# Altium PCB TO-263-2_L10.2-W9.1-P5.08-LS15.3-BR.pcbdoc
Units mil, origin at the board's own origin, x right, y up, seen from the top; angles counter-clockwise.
Board outline 1178.05 x 916 mil, 2 copper layers (Top Layer, Bottom Layer), stack 0 mil thick; 1 components, 0 nets, 3 pads, 0 vias.
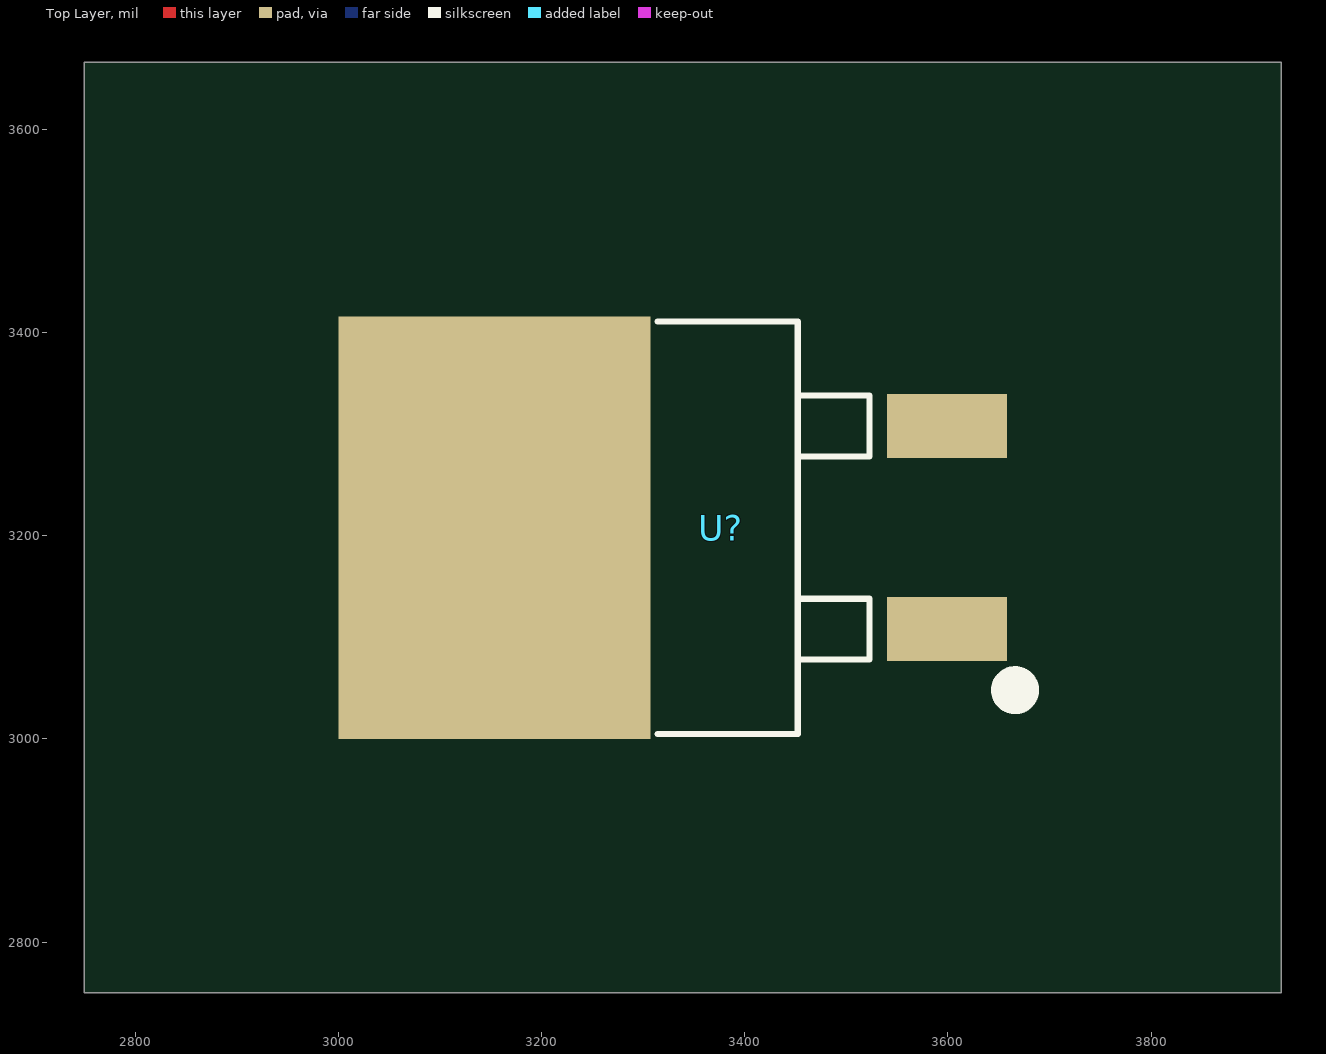
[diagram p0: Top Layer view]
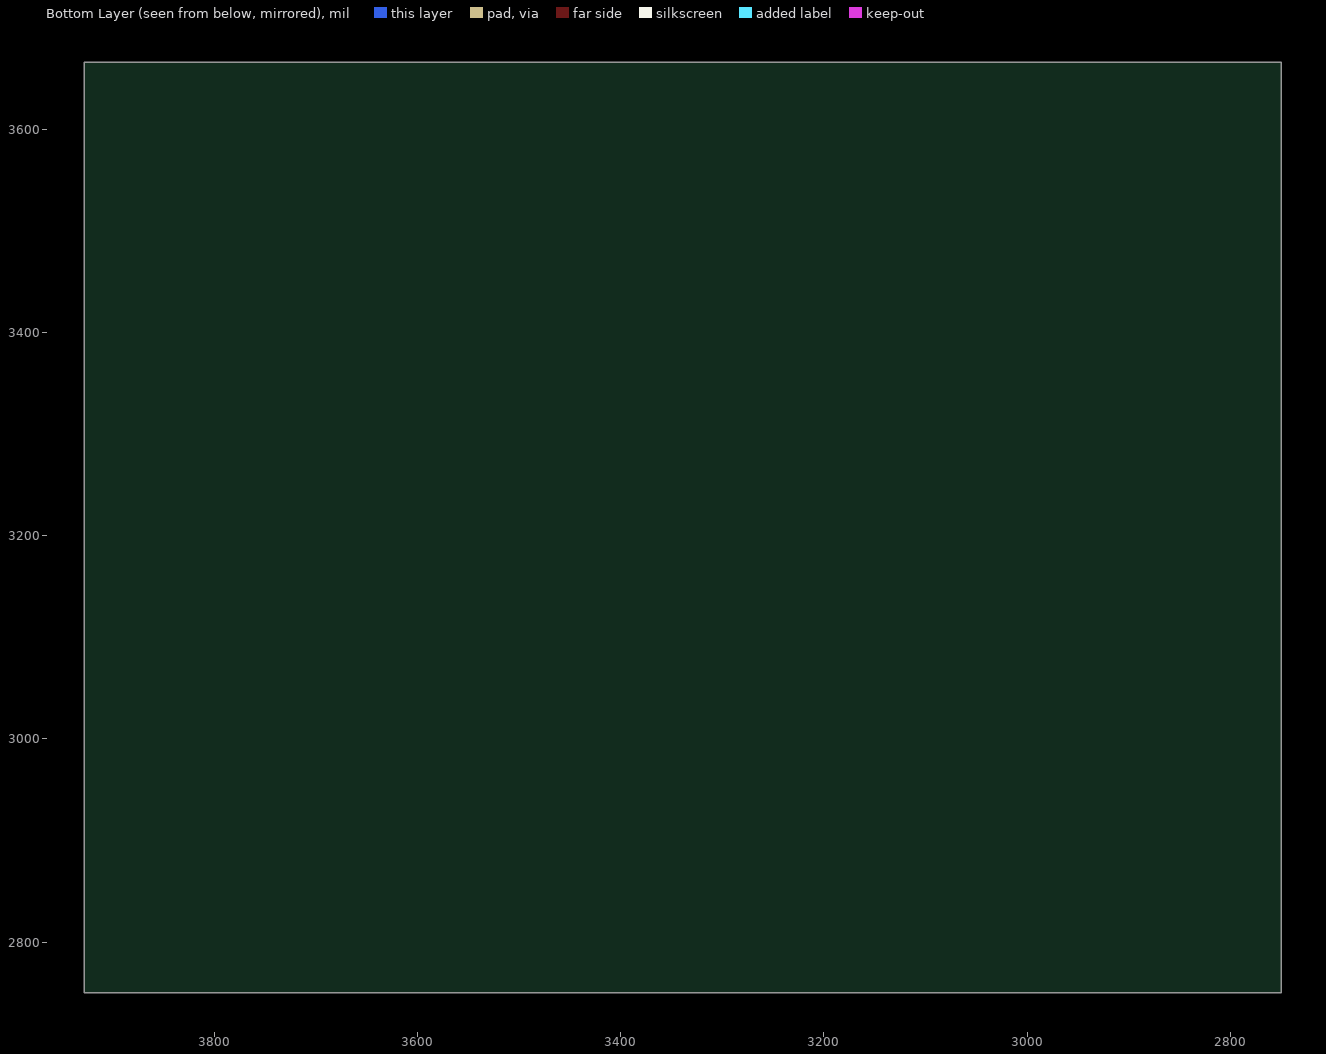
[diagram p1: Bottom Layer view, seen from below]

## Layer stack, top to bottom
Top Layer: signal copper (thickness not stored)
Bottom Layer: signal copper (thickness not stored)

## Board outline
3928.05,2750 2750,2750 2750,3666 3928.05,3666

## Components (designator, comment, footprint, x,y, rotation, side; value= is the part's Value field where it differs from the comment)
U? "" TO-263-2_L10.2-W9.1-P5.08-LS15.3-BR 3376.24,3208 r0 top

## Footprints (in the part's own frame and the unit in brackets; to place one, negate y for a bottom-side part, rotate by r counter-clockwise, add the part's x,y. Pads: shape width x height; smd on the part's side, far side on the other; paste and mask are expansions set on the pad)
TO-263-2_L10.2-W9.1-P5.08-LS15.3-BR [mm]
  rect 3x1.6 smd: 1(5.657,-2.54) 3(5.657,2.54)
  rect 7.8x10.566 smd: 2(-5.657,0)
  silkscreen extent -1.58,-5.16 7.67,5.16

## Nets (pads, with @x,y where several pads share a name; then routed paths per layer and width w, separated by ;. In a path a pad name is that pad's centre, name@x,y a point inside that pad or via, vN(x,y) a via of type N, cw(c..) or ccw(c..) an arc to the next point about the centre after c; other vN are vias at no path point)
pads on no net: U?.1 U?.2 U?.3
